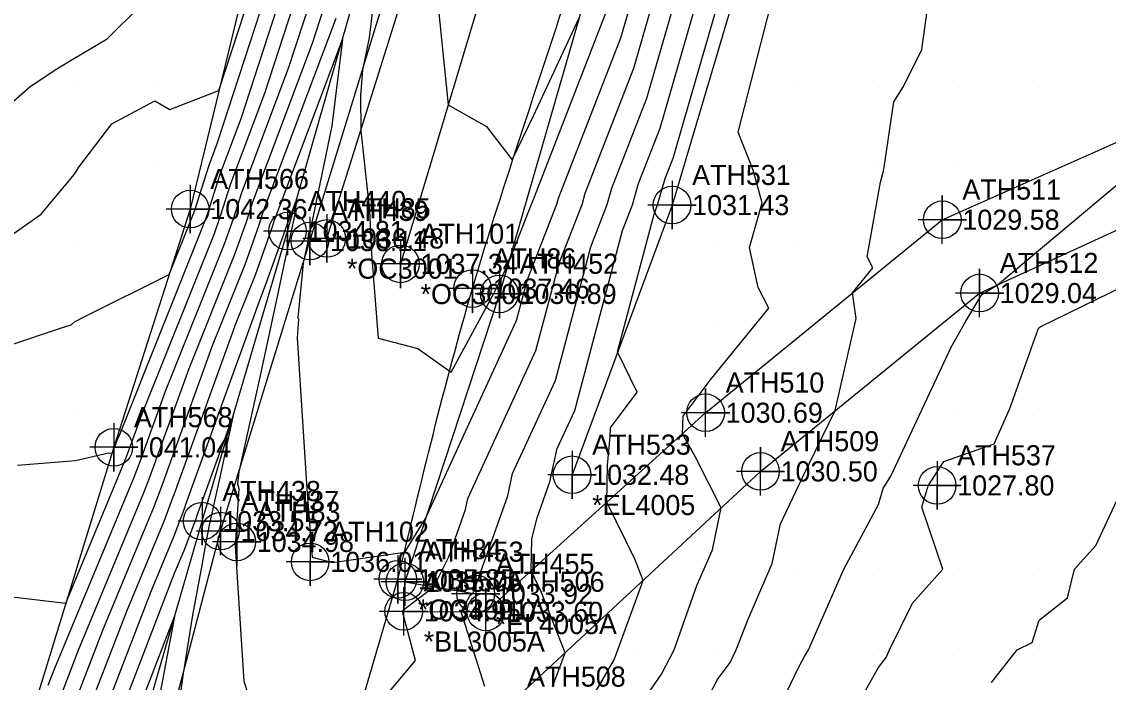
# Model space of a CAD drawing. Extents: x 1213164 to 1213550, y 766120 to 766870.
# Drawn here: x 1213343.5 to 1213478.6, y 766656 to 766738.1 of the extents above; entities that cross this region are included whole.
import ezdxf

# ---------------------------------------------------------------- set-up
doc = ezdxf.new("R2010")
doc.units = 0
for name, color, linetype in [('Default', 7, 'Continuous'), ('Exist DTM Breakline', 7, 'Continuous'), ('Exist DTM Breakline Cogo Comment', 7, 'Continuous'), ('Exist DTM Breakline Cogo Elevation', 7, 'Continuous'), ('Exist DTM Breakline Cogo Number', 7, 'Continuous'), ('Exist DTM Breakline Cogo Point CELL', 7, 'Continuous'), ('Exist DTM Crownline', 7, 'Continuous'), ('Exist DTM Crownline Cogo Comment', 7, 'Continuous'), ('Exist DTM Crownline Cogo Elevation', 7, 'Continuous'), ('Exist DTM Crownline Cogo Number', 7, 'Continuous'), ('Exist DTM Crownline Cogo Point CELL', 7, 'Continuous'), ('Exist DTM QL2 LIDAR Elevation Point', 7, 'Continuous'), ('Exist DTM Regular Point CELL', 7, 'Continuous'), ('Exist DTM Regular Point Cogo Elevation', 7, 'Continuous'), ('Exist DTM Regular Point Cogo Number', 7, 'Continuous'), ('Exist Roads EOP', 7, 'Continuous'), ('Exist Roads EOP Cogo Comment', 7, 'Continuous'), ('Exist Roads EOP Cogo Elevation', 7, 'Continuous'), ('Exist Roads EOP Cogo Number', 7, 'Continuous'), ('Exist Roads EOP Cogo Point CELL', 7, 'Continuous'), ('Exist Roads Soil', 7, 'Continuous'), ('Exist Roads Soil Cogo Comment', 7, 'Continuous'), ('Exist Roads Soil Cogo Elevation', 7, 'Continuous'), ('Exist Roads Soil Cogo Number', 7, 'Continuous'), ('Exist Roads Soil Cogo Point CELL', 7, 'Continuous')]:
    doc.layers.add(name, color=color, linetype=linetype)

msp = doc.modelspace()

# ---------------------------------------------------------------- linework, layer by layer
at = {"layer": 'Default'}
for points in [[(1213342.11, 766727.89), (1213344.49, 766730), (1213347.81, 766732.19), (1213350, 766733.54), (1213354.07, 766735.93), (1213358.17, 766740), (1213359.01, 766740.99), (1213360, 766742.21), (1213370.38, 766750.08), (1213371.54, 766754.87), (1213373.75, 766752.91), (1213380.81, 766772.67), (1213381.86, 766775.89), (1213389.86, 766798.56), (1213391.32, 766803.05), (1213392.08, 766805.9), (1213394.22, 766814.38), (1213399.26, 766833.49), (1213403.67, 766833.87), (1213411.11, 766832.9)], [(1213340, 766710.04), (1213345.86, 766714.14), (1213350, 766719.11), (1213350.56, 766720), (1213354.65, 766725.35), (1213360, 766728.23), (1213361.87, 766727.15), (1213367.98, 766729.52), (1213374.34, 766749.03), (1213374.82, 766750.27), (1213381.78, 766769.73), (1213384, 766776.55), (1213390.8, 766795.81), (1213392.96, 766802.49), (1213393.6, 766804.88), (1213396.69, 766817.13), (1213400.72, 766832.38), (1213406.29, 766832.86), (1213415.68, 766831.63)], [(1213342.11, 766697.89), (1213348.38, 766700), (1213349.6, 766700.4), (1213350, 766700.74), (1213351.46, 766701.5), (1213361.8, 766706.63), (1213364.87, 766714.3), (1213364.99, 766714.64), (1213366.77, 766720.25), (1213367.78, 766722.94), (1213375.88, 766747.81), (1213376.91, 766750.46), (1213382.75, 766766.79), (1213386.14, 766777.21), (1213391.74, 766793.06), (1213394.61, 766801.93), (1213395.13, 766803.87), (1213399.16, 766819.87), (1213402.17, 766831.27), (1213408.9, 766831.85), (1213420.25, 766830.36)], [(1213414.88, 766654.88), (1213417.13, 766658.74), (1213420.74, 766668.62), (1213419.75, 766671.17), (1213416.21, 766678.32), (1213416.32, 766682.92), (1213416.64, 766686.47), (1213416.69, 766687.59), (1213419.98, 766692), (1213417.57, 766697.03), (1213422.1, 766714.12), (1213422.55, 766715.28), (1213423.5, 766718.57), (1213424.48, 766721.09), (1213432.07, 766747.34)], [(1213342.93, 766682.93), (1213350.15, 766683.51), (1213354.23, 766684.47), (1213354.68, 766684.42), (1213354.96, 766685.09), (1213354.97, 766685.11), (1213355.38, 766686.11), (1213355.51, 766686.48), (1213366.15, 766713.02), (1213366.59, 766714.28), (1213368.12, 766719.11), (1213370.73, 766726.05), (1213377.43, 766746.6)], [(1213401.07, 766655.44), (1213398.13, 766664.72), (1213399.24, 766666.78), (1213399.54, 766667.01), (1213399.68, 766667.27), (1213403.9, 766679.13), (1213404.51, 766681.89), (1213409.83, 766693.47), (1213414.22, 766710.07), (1213416.28, 766715.33), (1213416.87, 766717.36), (1213421.22, 766728.56), (1213426.36, 766746.32)], [(1213409.49, 766655.4), (1213411.03, 766659.6), (1213408.12, 766667.12), (1213406.8, 766669.79), (1213406.9, 766673.78), (1213407.57, 766676.39), (1213409.15, 766680.85), (1213410.06, 766685), (1213412.24, 766689.73), (1213418.16, 766712.09), (1213419.42, 766715.3), (1213420.18, 766717.96), (1213422.85, 766724.82), (1213429.21, 766746.83)], [(1213341.5, 766666.67), (1213348.94, 766665.78), (1213356.2, 766683.27), (1213356.43, 766683.89), (1213356.79, 766684.75), (1213358.43, 766689.31), (1213367.42, 766711.74), (1213368.19, 766713.92), (1213369.47, 766717.97), (1213373.69, 766729.17), (1213378.97, 766745.39)], [(1213350.78, 766649.9), (1213356.51, 766664.8), (1213361.16, 766675.99), (1213362.3, 766678.99), (1213362.43, 766679.31), (1213370.12, 766700.64), (1213372.51, 766706.6), (1213374.59, 766712.47), (1213374.89, 766713.4), (1213383.33, 766735.85), (1213382.03, 766725.12), (1213379.06, 766710.9), (1213378.96, 766710.39), (1213378.44, 766708.05), (1213378.21, 766705.5), (1213377.81, 766701.25), (1213377.86, 766701.07), (1213377.72, 766698.75), (1213378.9, 766679.98), (1213379.57, 766671.51), (1213382.09, 766670.86), (1213391.1, 766672.13), (1213393.55, 766676.09), (1213393.73, 766676.41), (1213405, 766700.93), (1213406.35, 766706.03), (1213410.01, 766715.37), (1213410.23, 766716.15), (1213417.97, 766736.04), (1213420.65, 766745.31)], [(1213384.51, 766649.22), (1213392.44, 766658.66), (1213390.81, 766664.73), (1213390.92, 766665), (1213390.97, 766665.01), (1213394.71, 766667.82), (1213396.56, 766671.55), (1213398.65, 766677.42), (1213398.95, 766678.79), (1213407.41, 766697.2), (1213410.29, 766708.05), (1213413.14, 766715.35), (1213413.55, 766716.76), (1213419.6, 766732.3), (1213423.5, 766745.82)], [(1213346.76, 766655.58), (1213347.59, 766657.72), (1213357.44, 766681.45), (1213357.9, 766682.66), (1213358.2, 766683.39), (1213361.35, 766692.14), (1213368.69, 766710.45), (1213369.79, 766713.55), (1213370.83, 766716.83), (1213376.64, 766732.28), (1213380.52, 766744.18)], [(1213348.1, 766653.69), (1213350.56, 766660.08), (1213358.68, 766679.63), (1213359.37, 766681.44), (1213359.61, 766682.03), (1213364.28, 766694.97), (1213369.97, 766709.17), (1213371.39, 766713.19), (1213372.18, 766715.69), (1213379.6, 766735.4), (1213382.06, 766742.97)], [(1213394.97, 766742.85), (1213396.5, 766727.72), (1213401.28, 766725.03), (1213404.44, 766720.91), (1213407.12, 766726.37), (1213412.78, 766738.54)], [(1213387.11, 766739.86), (1213386.65, 766736.07), (1213385.82, 766732.09), (1213385.59, 766728.91), (1213385.61, 766724.5), (1213386.69, 766714.59), (1213386.95, 766709.21), (1213387.77, 766698.71), (1213392.7, 766697.45), (1213396.85, 766694.52), (1213402.2, 766704.36), (1213402.81, 766705.51), (1213403.88, 766707.74), (1213406.87, 766715.39), (1213406.92, 766715.55), (1213416.34, 766739.78)], [(1213420, 766652.57), (1213423.02, 766656.98), (1213424.59, 766660), (1213427.43, 766668), (1213429.35, 766672.43), (1213430.45, 766677.63), (1213427.24, 766683.94), (1213425.63, 766686.85), (1213425.74, 766689.03), (1213429.08, 766693.51), (1213436.37, 766702.46), (1213435.03, 766705.03), (1213433.98, 766710), (1213435.54, 766715.54), (1213434.44, 766719.59), (1213432.56, 766724.35), (1213436.58, 766740.01)], [(1213427.85, 766652.15), (1213430, 766656.29), (1213431.57, 766658.43), (1213432.32, 766660), (1213433.81, 766663.81), (1213436.81, 766670.73), (1213437.84, 766675.64), (1213440.56, 766681.4), (1213444.63, 766689.72), (1213447.24, 766701.19), (1213446.8, 766704.37), (1213449.32, 766707.46), (1213448.6, 766708.83), (1213450.28, 766718.13), (1213450.62, 766719.49), (1213450.73, 766720), (1213451.91, 766728.09), (1213453.14, 766730), (1213455.41, 766734.59), (1213456.17, 766740)], [(1213349.44, 766651.8), (1213353.54, 766662.44), (1213359.92, 766677.81), (1213360.83, 766680.21), (1213361.02, 766680.67), (1213367.2, 766697.81), (1213371.24, 766707.89), (1213372.99, 766712.83), (1213373.54, 766714.54), (1213382.55, 766738.51)], [(1213437.52, 766652.48), (1213440, 766657.61), (1213440.83, 766659.17), (1213441.3, 766660), (1213443.95, 766666.05), (1213445.7, 766670), (1213450, 766678.06), (1213450.58, 766680.03), (1213451.57, 766681.57), (1213459.04, 766697.61), (1213460.9, 766700.86), (1213462.89, 766704.16), (1213464.83, 766705.35), (1213486.46, 766723.48)], [(1213352.12, 766648.01), (1213359.49, 766667.16), (1213362.4, 766674.17), (1213363.76, 766677.76), (1213363.84, 766677.95), (1213373.05, 766703.47), (1213373.79, 766705.32), (1213376.2, 766712.11), (1213376.24, 766712.26), (1213377.62, 766715.91), (1213377.4, 766714.16), (1213376.92, 766711.85), (1213375.78, 766706.49), (1213375.29, 766704.26), (1213373, 766693.5), (1213370.44, 766682.11), (1213370.3, 766680.61), (1213370.45, 766680.02), (1213370.02, 766672.86), (1213371.08, 766656.07), (1213373.25, 766649.48)], [(1213464.06, 766655.94), (1213467.28, 766660), (1213469.12, 766660.88), (1213470, 766663.66), (1213473.54, 766666.46), (1213474.4, 766670), (1213477.04, 766672.96), (1213480, 766679.24), (1213480.39, 766679.61), (1213480.99, 766680), (1213486.65, 766683.35), (1213490, 766687.67), (1213490.42, 766689.43), (1213493.65, 766690), (1213498.42, 766691.58), (1213500, 766692.24), (1213507.38, 766692.62), (1213510, 766694.38), (1213513.24, 766696.76), (1213515.3, 766700), (1213518.27, 766701.73), (1213520, 766703.15), (1213527.93, 766707.93), (1213530, 766708.58)], [(1213447.2, 766652.8), (1213450, 766657.79), (1213450.96, 766659.04), (1213451.38, 766660), (1213454.23, 766665.77), (1213458.02, 766670), (1213455.41, 766677.71), (1213456.19, 766680.36), (1213458.15, 766683.4), (1213464.4, 766685.6), (1213466.36, 766690), (1213469.86, 766699.86), (1213469.94, 766700.01), (1213469.96, 766700.03), (1213470.22, 766700.19), (1213484.07, 766706.95)], [(1213353.46, 766646.12), (1213362.47, 766669.52), (1213363.64, 766672.35), (1213365.23, 766676.53), (1213365.25, 766676.59), (1213369.71, 766688.95), (1213368.11, 766681.44), (1213366.77, 766675.5), (1213366.27, 766672.88), (1213365.87, 766670.53), (1213364.7, 766664.3), (1213363.53, 766657.03), (1213362.49, 766649.7)], [(1213354.8, 766644.23), (1213362.46, 766664.13), (1213360.44, 766653.35)]]:
    msp.add_lwpolyline(points, dxfattribs=at)
at = {"layer": 'Exist DTM Breakline'}
for points in [[(1213393.73, 766837.71), (1213387.94, 766804.2), (1213372.97, 766750.1), (1213364.41, 766714.77), (1213354.91, 766685.16), (1213342.45, 766644.74), (1213315.98, 766668.51), (1213286.51, 766700.01), (1213270.13, 766717.65)], [(1213346.63, 766614.52), (1213356.15, 766642.33), (1213365.89, 766675.98), (1213376.51, 766712.04), (1213387.8, 766751.44), (1213401.65, 766799.53), (1213406.48, 766827.99)], [(1213348.97, 766613.21), (1213359.36, 766641.08), (1213368.17, 766674.74), (1213379.29, 766710.8), (1213391.46, 766750.47), (1213404.9, 766798.24), (1213409.09, 766827.1)], [(1213432.48, 766824.57), (1213426.44, 766793.4), (1213414.42, 766744.2), (1213402.86, 766704.23), (1213391.11, 766668.44), (1213399.92, 766666.94)], [(1213447.89, 766819.84), (1213441.94, 766786.26), (1213433.96, 766747.68), (1213424.34, 766715.27), (1213411.9, 766681.74)]]:
    msp.add_lwpolyline(points, dxfattribs=at)
at = {"layer": 'Exist DTM Breakline Cogo Point CELL'}
for points in [[(1213364.41, 766717.77), (1213364.41, 766711.77), (1213364.41, 766714.77), (1213367.41, 766714.77), (1213361.41, 766714.77)], [(1213424.34, 766718.27), (1213424.34, 766712.27), (1213424.34, 766715.27), (1213427.34, 766715.27), (1213421.34, 766715.27)], [(1213376.51, 766715.04), (1213376.51, 766709.04), (1213376.51, 766712.04), (1213379.51, 766712.04), (1213373.51, 766712.04)], [(1213379.29, 766713.8), (1213379.29, 766707.8), (1213379.29, 766710.8), (1213382.29, 766710.8), (1213376.29, 766710.8)], [(1213402.86, 766707.23), (1213402.86, 766701.23), (1213402.86, 766704.23), (1213405.86, 766704.23), (1213399.86, 766704.23)], [(1213354.91, 766688.16), (1213354.91, 766682.16), (1213354.91, 766685.16), (1213357.91, 766685.16), (1213351.91, 766685.16)], [(1213411.9, 766684.74), (1213411.9, 766678.74), (1213411.9, 766681.74), (1213414.9, 766681.74), (1213408.9, 766681.74)], [(1213365.89, 766678.98), (1213365.89, 766672.98), (1213365.89, 766675.98), (1213368.89, 766675.98), (1213362.89, 766675.98)], [(1213368.17, 766677.74), (1213368.17, 766671.74), (1213368.17, 766674.74), (1213371.17, 766674.74), (1213365.17, 766674.74)], [(1213391.11, 766671.44), (1213391.11, 766665.44), (1213391.11, 766668.44), (1213394.11, 766668.44), (1213388.11, 766668.44)], [(1213399.92, 766669.94), (1213399.92, 766663.94), (1213399.92, 766666.94), (1213402.92, 766666.94), (1213396.92, 766666.94)]]:
    msp.add_lwpolyline(points, dxfattribs=at)
for centre in [(1213424.34, 766715.27), (1213364.41, 766714.77), (1213376.51, 766712.04), (1213379.29, 766710.8), (1213402.86, 766704.23), (1213354.91, 766685.16), (1213411.9, 766681.74), (1213365.89, 766675.98), (1213368.17, 766674.74), (1213391.11, 766668.44), (1213399.92, 766666.94)]:
    msp.add_circle(centre, 2.34, dxfattribs=at)
at = {"layer": 'Exist DTM Crownline'}
msp.add_line((1213402.62, 766748.09), (1213390.56, 766707.96), dxfattribs=at)
at = {"layer": 'Exist DTM Crownline Cogo Point CELL'}
for points in [[(1213390.56, 766710.96), (1213390.56, 766704.96), (1213390.56, 766707.96), (1213393.56, 766707.96), (1213387.56, 766707.96)], [(1213379.33, 766673.92), (1213379.33, 766667.92), (1213379.33, 766670.92), (1213382.33, 766670.92), (1213376.33, 766670.92)]]:
    msp.add_lwpolyline(points, dxfattribs=at)
for centre in [(1213390.56, 766707.96), (1213379.33, 766670.92)]:
    msp.add_circle(centre, 2.34, dxfattribs=at)
at = {"layer": 'Exist DTM QL2 LIDAR Elevation Point'}
for p, q in [((1213350, 766730), (1213350, 766730)), ((1213360, 766730), (1213360, 766730)), ((1213440, 766730), (1213440, 766730)), ((1213450, 766730), (1213450, 766730)), ((1213460, 766730), (1213460, 766730)), ((1213470, 766730), (1213470, 766730)), ((1213350, 766720), (1213350, 766720)), ((1213360, 766720), (1213360, 766720)), ((1213440, 766720), (1213440, 766720)), ((1213450, 766720), (1213450, 766720)), ((1213460, 766720), (1213460, 766720)), ((1213350, 766710), (1213350, 766710)), ((1213430, 766710), (1213430, 766710)), ((1213440, 766710), (1213440, 766710)), ((1213350, 766700), (1213350, 766700)), ((1213430, 766700), (1213430, 766700)), ((1213470, 766700), (1213470, 766700)), ((1213350, 766690), (1213350, 766690)), ((1213460, 766690), (1213460, 766690)), ((1213470, 766690), (1213470, 766690)), ((1213450, 766680), (1213450, 766680)), ((1213470, 766680), (1213470, 766680)), ((1213440, 766670), (1213440, 766670)), ((1213450, 766670), (1213450, 766670)), ((1213460, 766670), (1213460, 766670)), ((1213470, 766670), (1213470, 766670)), ((1213420, 766660), (1213420, 766660)), ((1213430, 766660), (1213430, 766660)), ((1213440, 766660), (1213440, 766660)), ((1213450, 766660), (1213450, 766660)), ((1213460, 766660), (1213460, 766660)), ((1213470, 766660), (1213470, 766660))]:
    msp.add_line(p, q, dxfattribs=at)
at = {"layer": 'Exist DTM Regular Point CELL'}
msp.add_lwpolyline([(1213457.31, 766683.42), (1213457.31, 766677.42), (1213457.31, 766680.42), (1213460.31, 766680.42), (1213454.31, 766680.42)], dxfattribs=at)
msp.add_circle((1213457.31, 766680.42), 2.34, dxfattribs=at)
at = {"layer": 'Exist Roads EOP'}
msp.add_line((1213381.4, 766711.12), (1213393.64, 766750.06), dxfattribs=at)
msp.add_lwpolyline([(1213344.56, 766509.06), (1213357.66, 766555.92), (1213369.4, 766599.7), (1213380.5, 766635.51), (1213390.23, 766668.75)], dxfattribs=at)
msp.add_spline([(1213390.23, 766668.75), (1213399.52, 766704.89), (1213412.3, 766744.74), (1213425.35, 766793.62), (1213431.78, 766824.82)], degree=3, dxfattribs=at)
at = {"layer": 'Exist Roads EOP Cogo Point CELL'}
for points in [[(1213381.4, 766714.12), (1213381.4, 766708.12), (1213381.4, 766711.12), (1213384.4, 766711.12), (1213378.4, 766711.12)], [(1213399.52, 766707.89), (1213399.52, 766701.89), (1213399.52, 766704.89), (1213402.52, 766704.89), (1213396.52, 766704.89)], [(1213370.19, 766676.4), (1213370.19, 766670.4), (1213370.19, 766673.4), (1213373.19, 766673.4), (1213367.19, 766673.4)], [(1213390.23, 766671.75), (1213390.23, 766665.75), (1213390.23, 766668.75), (1213393.23, 766668.75), (1213387.23, 766668.75)]]:
    msp.add_lwpolyline(points, dxfattribs=at)
for centre in [(1213381.4, 766711.12), (1213399.52, 766704.89), (1213370.19, 766673.4), (1213390.23, 766668.75)]:
    msp.add_circle(centre, 2.34, dxfattribs=at)
at = {"layer": 'Exist Roads Soil'}
for points in [[(1213390.96, 766664.77), (1213401.18, 766664.7), (1213428.51, 766689.46), (1213457.95, 766713.45), (1213492.62, 766728.87)], [(1213380.26, 766624.46), (1213403.81, 766652.91), (1213435.34, 766682.17), (1213462.6, 766704.33), (1213495.25, 766719.33)]]:
    msp.add_lwpolyline(points, dxfattribs=at)
at = {"layer": 'Exist Roads Soil Cogo Point CELL'}
for points in [[(1213457.95, 766710.45), (1213457.95, 766716.45), (1213457.95, 766713.45), (1213460.95, 766713.45), (1213454.95, 766713.45)], [(1213462.6, 766701.33), (1213462.6, 766707.33), (1213462.6, 766704.33), (1213465.6, 766704.33), (1213459.6, 766704.33)], [(1213428.51, 766686.46), (1213428.51, 766692.46), (1213428.51, 766689.46), (1213431.51, 766689.46), (1213425.51, 766689.46)], [(1213435.34, 766679.17), (1213435.34, 766685.17), (1213435.34, 766682.17), (1213438.34, 766682.17), (1213432.34, 766682.17)], [(1213390.96, 766661.77), (1213390.96, 766667.77), (1213390.96, 766664.77), (1213393.96, 766664.77), (1213387.96, 766664.77)], [(1213401.18, 766661.7), (1213401.18, 766667.7), (1213401.18, 766664.7), (1213404.18, 766664.7), (1213398.18, 766664.7)]]:
    msp.add_lwpolyline(points, dxfattribs=at)
for centre in [(1213457.95, 766713.45), (1213462.6, 766704.33), (1213428.51, 766689.46), (1213435.34, 766682.17), (1213390.96, 766664.77), (1213401.18, 766664.7)]:
    msp.add_circle(centre, 2.34, dxfattribs=at)

# ---------------------------------------------------------------- texts
at = {"layer": 'Exist DTM Breakline Cogo Comment'}
for s, p in [('*EL4005', (1213414.4, 766676.74)), ('*EL4005A', (1213402.42, 766661.94))]:
    msp.add_text(s, height=2.5, dxfattribs=at).set_placement(p)
at = {"layer": 'Exist DTM Breakline Cogo Elevation'}
for s, p in [('1031.43', (1213426.84, 766714.02)), ('1042.36', (1213366.91, 766713.52)), ('1034.81', (1213379.01, 766710.79)), ('1036.11', (1213381.79, 766709.55)), ('1036.89', (1213405.36, 766702.98)), ('1041.04', (1213357.41, 766683.91)), ('1032.48', (1213414.4, 766680.49)), ('1033.55', (1213368.39, 766674.73)), ('1034.72', (1213370.67, 766673.49)), ('1035.75', (1213393.61, 766667.19)), ('1033.92', (1213402.42, 766665.69))]:
    msp.add_text(s, height=2.5, dxfattribs=at).set_placement(p)
at = {"layer": 'Exist DTM Breakline Cogo Number'}
for s, p in [('ATH566', (1213366.91, 766717.27)), ('ATH531', (1213426.84, 766717.77)), ('ATH440', (1213379.01, 766714.54)), ('ATH439', (1213381.79, 766713.3)), ('ATH452', (1213405.36, 766706.73)), ('ATH568', (1213357.41, 766687.66)), ('ATH533', (1213414.4, 766684.24)), ('ATH438', (1213368.39, 766678.48)), ('ATH437', (1213370.67, 766677.24)), ('ATH453', (1213393.61, 766670.94)), ('ATH455', (1213402.42, 766669.44))]:
    msp.add_text(s, height=2.5, dxfattribs=at).set_placement(p)
at = {"layer": 'Exist DTM Crownline Cogo Comment'}
msp.add_text('*OC3008', height=2.5, dxfattribs=at).set_placement((1213393.06, 766702.96))
at = {"layer": 'Exist DTM Crownline Cogo Elevation'}
for s, p in [('1037.34', (1213393.06, 766706.71)), ('1036.01', (1213381.83, 766669.67))]:
    msp.add_text(s, height=2.5, dxfattribs=at).set_placement(p)
at = {"layer": 'Exist DTM Crownline Cogo Number'}
for s, p in [('ATH101', (1213393.06, 766710.46)), ('ATH102', (1213381.83, 766673.42))]:
    msp.add_text(s, height=2.5, dxfattribs=at).set_placement(p)
at = {"layer": 'Exist DTM Regular Point Cogo Elevation'}
msp.add_text('1027.80', height=2.5, dxfattribs=at).set_placement((1213459.81, 766679.17))
at = {"layer": 'Exist DTM Regular Point Cogo Number'}
msp.add_text('ATH537', height=2.5, dxfattribs=at).set_placement((1213459.81, 766682.92))
at = {"layer": 'Exist Roads EOP Cogo Comment'}
for s, p in [('*OC3001', (1213383.9, 766706.12)), ('*OC3001A', (1213392.73, 766663.75))]:
    msp.add_text(s, height=2.5, dxfattribs=at).set_placement(p)
at = {"layer": 'Exist Roads EOP Cogo Elevation'}
for s, p in [('1036.48', (1213383.9, 766709.87)), ('1037.46', (1213402.02, 766703.64)), ('1034.98', (1213372.69, 766672.15)), ('1035.85', (1213392.73, 766667.5))]:
    msp.add_text(s, height=2.5, dxfattribs=at).set_placement(p)
at = {"layer": 'Exist Roads EOP Cogo Number'}
for s, p in [('ATH85', (1213383.9, 766713.62)), ('ATH86', (1213402.02, 766707.39)), ('ATH83', (1213372.69, 766675.9)), ('ATH84', (1213392.73, 766671.25))]:
    msp.add_text(s, height=2.5, dxfattribs=at).set_placement(p)
at = {"layer": 'Exist Roads Soil Cogo Comment'}
msp.add_text('*BL3005A', height=2.5, dxfattribs=at).set_placement((1213393.46, 766659.77))
at = {"layer": 'Exist Roads Soil Cogo Elevation'}
for s, p in [('1029.58', (1213460.45, 766712.2)), ('1029.04', (1213465.1, 766703.08)), ('1030.69', (1213431.01, 766688.21)), ('1030.50', (1213437.84, 766680.92)), ('1034.95', (1213393.46, 766663.52)), ('1033.60', (1213403.68, 766663.45))]:
    msp.add_text(s, height=2.5, dxfattribs=at).set_placement(p)
at = {"layer": 'Exist Roads Soil Cogo Number'}
for s, p in [('ATH511', (1213460.45, 766715.95)), ('ATH512', (1213465.1, 766706.83)), ('ATH510', (1213431.01, 766691.96)), ('ATH509', (1213437.84, 766684.67)), ('ATH505', (1213393.46, 766667.27)), ('ATH506', (1213403.68, 766667.2)), ('ATH508', (1213406.31, 766655.41))]:
    msp.add_text(s, height=2.5, dxfattribs=at).set_placement(p)

doc.saveas('drawing.dxf')
